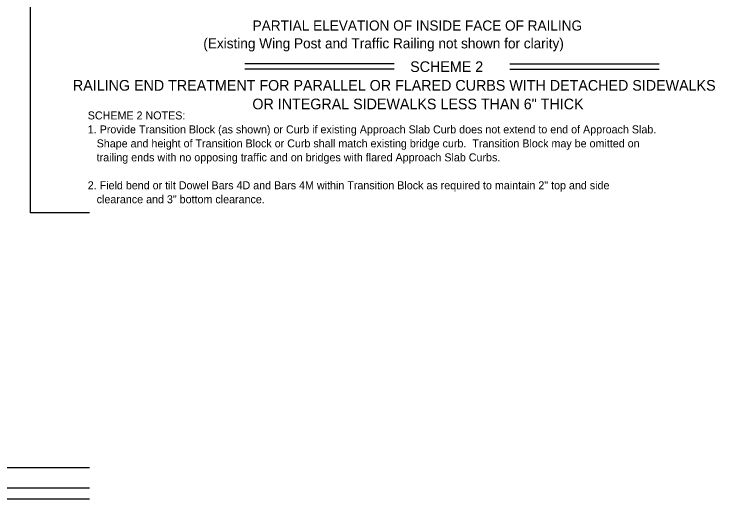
# Model space of a CAD drawing. Extents: x 21526.6 to 21598.7, y 56118.9 to 56155.9.
# Drawn here: x 21545.31 to 21562.95, y 56120.11 to 56132.33 of the extents above; entities that cross this region are included whole.
import ezdxf

# ---------------------------------------------------------------- set-up
doc = ezdxf.new("R2010")
doc.units = 0
doc.layers.add('Border', color=7, linetype='Continuous')
doc.layers.add('PlotBorder_dp', color=7, linetype='Continuous')

msp = doc.modelspace()

# ---------------------------------------------------------------- linework, layer by layer
at = {"layer": 'Border'}
for p, q in [((21547.212, 56120.898), (21526.6, 56120.898)), ((21547.212, 56120.383), (21526.6, 56120.383)), ((21526.6, 56120.11), (21547.212, 56120.11))]:
    msp.add_line(p, q, dxfattribs=at)
at = {"layer": 'PlotBorder_dp'}
for p, q in [((21545.716, 56153.256), (21545.716, 56127.317)), ((21554.877, 56131.073), (21551.118, 56131.073)), ((21557.792, 56131.073), (21561.551, 56131.073)), ((21554.877, 56130.939), (21551.118, 56130.939)), ((21557.792, 56130.939), (21561.551, 56130.939)), ((21547.212, 56127.317), (21545.716, 56127.317))]:
    msp.add_line(p, q, dxfattribs=at)

# ---------------------------------------------------------------- texts
for s, height, p in [('PARTIAL ELEVATION OF INSIDE FACE OF RAILING', 0.256, (21551.315, 56131.912)), ('(Existing Wing Post and Traffic Railing not shown for clarity)', 0.256, (21550.074, 56131.464)), ('SCHEME 2', 0.2688, (21555.281, 56130.87)), ('RAILING END TREATMENT FOR PARALLEL OR FLARED CURBS WITH DETACHED SIDEWALKS', 0.2688, (21546.792, 56130.399)), ('OR INTEGRAL SIDEWALKS LESS THAN 6" THICK', 0.2688, (21551.309, 56129.929)), ('SCHEME 2 NOTES:', 0.2016, (21547.165, 56129.674)), ('1. Provide Transition Block (as shown) or Curb if existing Approach Slab Curb does not extend to end of Approach Slab.  ', 0.2016, (21547.165, 56129.322)), ('   Shape and height of Transition Block or Curb shall match existing bridge curb.  Transition Block may be omitted on ', 0.2016, (21547.165, 56128.97)), ('   trailing ends with no opposing traffic and on bridges with flared Approach Slab Curbs.', 0.2016, (21547.165, 56128.618)), ('2. Field bend or tilt Dowel Bars 4D and Bars 4M within Transition Block as required to maintain 2" top and side', 0.2016, (21547.165, 56127.914)), ('   clearance and 3" bottom clearance.', 0.2016, (21547.165, 56127.562))]:
    msp.add_text(s, height=height, dxfattribs=at).set_placement(p)

doc.saveas('drawing.dxf')
